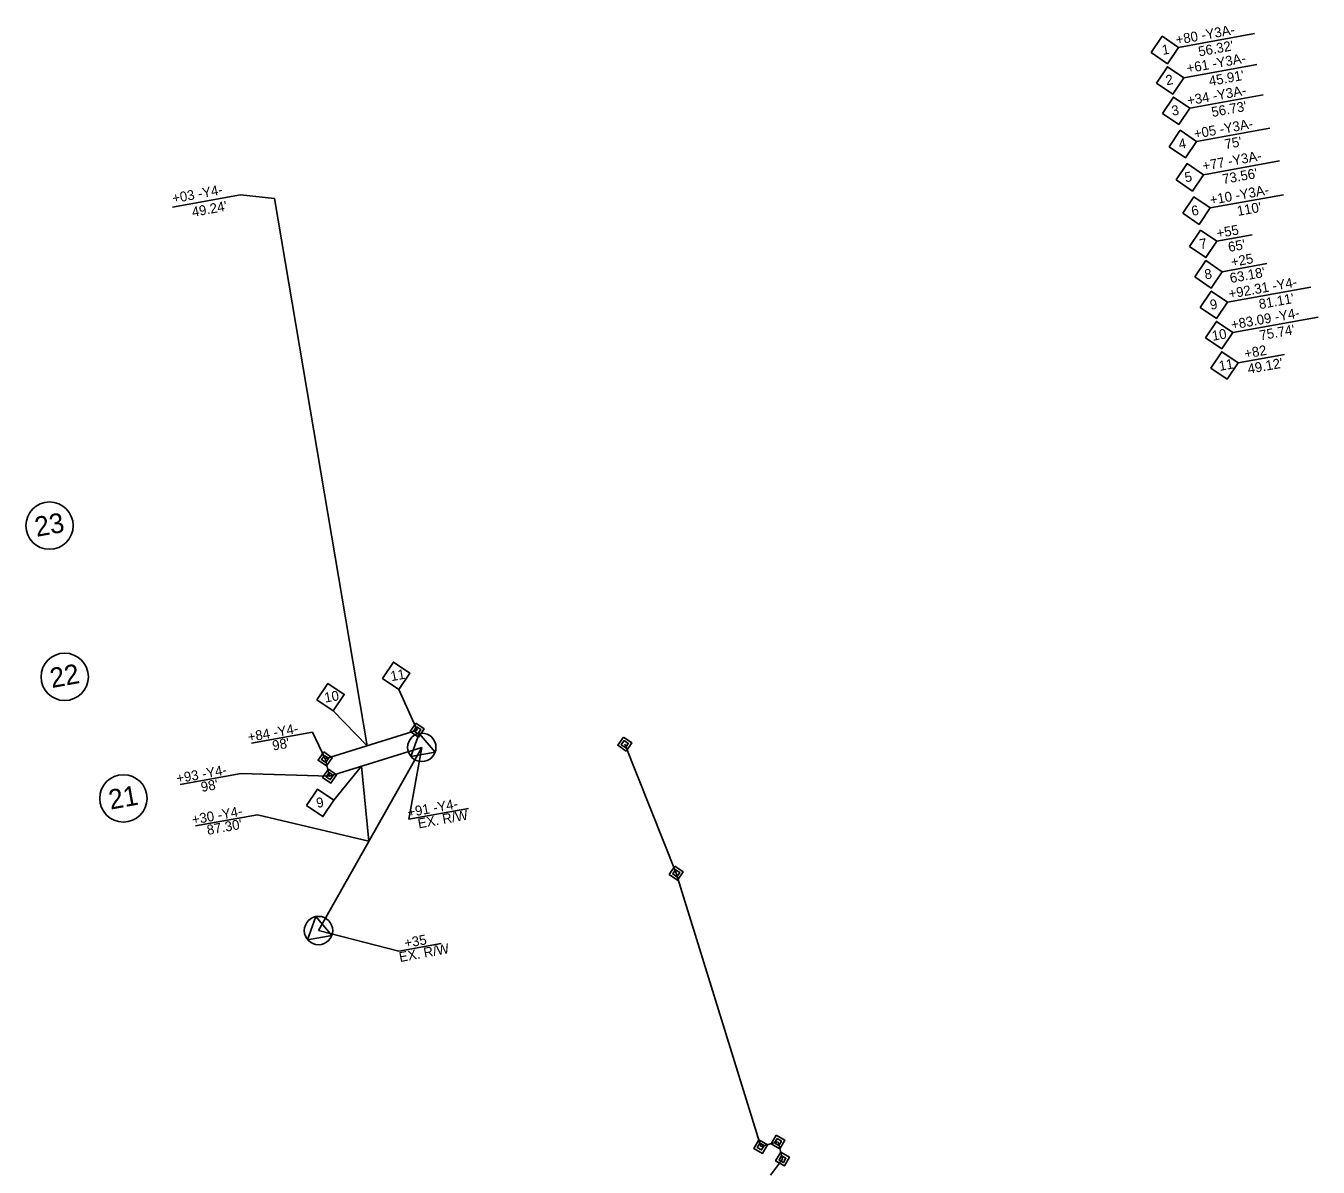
# Model space of a CAD drawing. Extents: x 1618217 to 1621927, y 897445 to 899141.
# Drawn here: x 1621192 to 1621847, y 898125 to 898703 of the extents above; entities that cross this region are included whole.
import ezdxf

# ---------------------------------------------------------------- set-up
doc = ezdxf.new("R2010")
doc.units = 0
for name, color, linetype in [('Prop Easement Construction', 7, 'Continuous'), ('Prop Easement Construction Station Offsets', 7, 'Continuous'), ('Prop Easement Permanent Utility', 7, 'Continuous'), ('Prop Easement Permanent Utility Station Offsets', 7, 'Continuous'), ('Prop Easement Temporary Drainage Station Offsets', 7, 'Continuous'), ('Prop Parcel Number CELL', 7, 'Continuous'), ('Prop ROW Marker CELL', 7, 'Continuous'), ('Prop ROW Permanent Easement CELL', 7, 'Continuous'), ('Prop ROW RW Lines', 7, 'Continuous'), ('Prop ROW Station Offsets', 7, 'Continuous')]:
    doc.layers.add(name, color=color, linetype=linetype)

msp = doc.modelspace()

# ---------------------------------------------------------------- linework, layer by layer
at = {"layer": 'Prop Easement Construction'}
for p, q in [((1621365.15, 898338.17), (1621318.33, 898615.59)), ((1621366.11, 898289.87), (1621362.35, 898327.88))]:
    msp.add_line(p, q, dxfattribs=at)
at = {"layer": 'Prop Easement Construction Station Offsets'}
for p, q in [((1621782.34, 898661.5), (1621819.53, 898668.23)), ((1621785.78, 898644.61), (1621822.97, 898651.34)), ((1621266.61, 898611.28), (1621301.06, 898617.52)), ((1621301.06, 898617.52), (1621318.33, 898615.59)), ((1621792.66, 898610.85), (1621829.85, 898617.58)), ((1621796.1, 898593.96), (1621814.01, 898597.2)), ((1621801.46, 898563.15), (1621843.63, 898570.78)), ((1621804.15, 898547.74), (1621847.41, 898555.57)), ((1621365.15, 898338.17), (1621347.98, 898355.93)), ((1621348.37, 898310.62), (1621362.35, 898327.88)), ((1621278.26, 898297.6), (1621309.57, 898303.27)), ((1621309.57, 898303.27), (1621366.11, 898289.87))]:
    msp.add_line(p, q, dxfattribs=at)
for points in [[(1621768.46, 898658.82), (1621776.74, 898653.21), (1621782.34, 898661.5), (1621774.06, 898667.1)], [(1621771.9, 898641.93), (1621780.18, 898636.33), (1621785.78, 898644.61), (1621777.5, 898650.22)], [(1621778.78, 898608.17), (1621787.06, 898602.56), (1621792.66, 898610.85), (1621784.38, 898616.45)], [(1621782.22, 898591.28), (1621790.5, 898585.68), (1621796.1, 898593.96), (1621787.82, 898599.57)], [(1621787.58, 898560.47), (1621795.86, 898554.86), (1621801.46, 898563.15), (1621793.18, 898568.75)], [(1621790.26, 898545.06), (1621798.54, 898539.46), (1621804.15, 898547.74), (1621795.86, 898553.34)], [(1621339.7, 898361.53), (1621347.98, 898355.93), (1621353.58, 898364.21), (1621345.3, 898369.81)], [(1621334.48, 898307.94), (1621342.76, 898302.34), (1621348.37, 898310.62), (1621340.08, 898316.23)]]:
    msp.add_lwpolyline(points, close=True, dxfattribs=at)
at = {"layer": 'Prop Easement Permanent Utility'}
for p, q in [((1621343.89, 898331.54), (1621390.59, 898346.11)), ((1621521.92, 898273.6), (1621495.84, 898339.08)), ((1621346.21, 898322.84), (1621392.93, 898337.42)), ((1621346.21, 898322.84), (1621343.89, 898331.54)), ((1621564.76, 898135.04), (1621521.92, 898273.6)), ((1621573.5, 898137.36), (1621564.76, 898135.04)), ((1621573.54, 898137.37), (1621575.87, 898128.67)), ((1621569.74, 898120.49), (1621575.83, 898128.66))]:
    msp.add_line(p, q, dxfattribs=at)
at = {"layer": 'Prop Easement Permanent Utility Station Offsets'}
for p, q in [((1621779.28, 898676.88), (1621816.26, 898683.57)), ((1621789.22, 898627.73), (1621827.78, 898634.71)), ((1621806.83, 898532.33), (1621830.4, 898536.6)), ((1621390.59, 898346.11), (1621381.24, 898366.75)), ((1621306.54, 898339.45), (1621337.54, 898345.06)), ((1621337.54, 898345.06), (1621343.89, 898331.54)), ((1621270.43, 898318.51), (1621301.33, 898324.1)), ((1621301.33, 898324.1), (1621346.21, 898322.84))]:
    msp.add_line(p, q, dxfattribs=at)
for points in [[(1621765.4, 898674.2), (1621773.68, 898668.6), (1621779.28, 898676.88), (1621771, 898682.48)], [(1621775.34, 898625.05), (1621783.62, 898619.45), (1621789.22, 898627.73), (1621780.94, 898633.33)], [(1621792.94, 898529.65), (1621801.22, 898524.05), (1621806.83, 898532.33), (1621798.54, 898537.93)], [(1621372.95, 898372.35), (1621381.24, 898366.75), (1621386.84, 898375.03), (1621378.56, 898380.64)]]:
    msp.add_lwpolyline(points, close=True, dxfattribs=at)
at = {"layer": 'Prop Easement Temporary Drainage Station Offsets'}
msp.add_line((1621798.78, 898578.56), (1621821.36, 898582.64), dxfattribs=at)
msp.add_lwpolyline([(1621784.9, 898575.88), (1621793.18, 898570.27), (1621798.78, 898578.56), (1621790.5, 898584.16)], close=True, dxfattribs=at)
at = {"layer": 'Prop Parcel Number CELL'}
for p, q in [((1621204.18, 898449.81), (1621204.18, 898449.81)), ((1621211.87, 898373.17), (1621211.87, 898373.17)), ((1621241.63, 898311.53), (1621241.63, 898311.53))]:
    msp.add_line(p, q, dxfattribs=at)
for centre in [(1621204.18, 898449.81), (1621211.87, 898373.17), (1621241.63, 898311.53)]:
    msp.add_circle(centre, 12, dxfattribs=at)
at = {"layer": 'Prop ROW Marker CELL'}
for p, q in [((1621392.93, 898337.42), (1621392.93, 898337.42)), ((1621340.55, 898244.54), (1621340.55, 898244.54)), ((1621573.5, 898137.36), (1621573.5, 898137.36)), ((1621564.76, 898135.04), (1621564.76, 898135.04)), ((1621575.83, 898128.66), (1621575.83, 898128.66))]:
    msp.add_line(p, q, dxfattribs=at)
for points in [[(1621387.42, 898332.76), (1621391.65, 898344.5), (1621399.72, 898334.99)], [(1621335.04, 898239.89), (1621339.27, 898251.63), (1621347.34, 898242.11)]]:
    msp.add_lwpolyline(points, close=True, dxfattribs=at)
for centre in [(1621392.93, 898337.42), (1621340.55, 898244.54)]:
    msp.add_circle(centre, 7.2, dxfattribs=at)
at = {"layer": 'Prop ROW Permanent Easement CELL'}
for p, q in [((1621390.59, 898346.11), (1621390.59, 898346.11)), ((1621495.84, 898339.08), (1621495.84, 898339.08)), ((1621343.89, 898331.54), (1621343.89, 898331.54)), ((1621346.21, 898322.84), (1621346.21, 898322.84)), ((1621521.92, 898273.6), (1621521.92, 898273.6))]:
    msp.add_line(p, q, dxfattribs=at)
for points in [[(1621389.94, 898349.65), (1621394.13, 898346.75), (1621391.23, 898342.56), (1621387.04, 898345.46)], [(1621390.27, 898347.88), (1621392.36, 898346.43), (1621390.91, 898344.34), (1621388.81, 898345.79)], [(1621495.2, 898342.62), (1621499.38, 898339.72), (1621496.48, 898335.54), (1621492.3, 898338.44)], [(1621495.52, 898340.85), (1621497.61, 898339.4), (1621496.16, 898337.31), (1621494.07, 898338.76)], [(1621343.24, 898335.08), (1621347.43, 898332.18), (1621344.53, 898327.99), (1621340.34, 898330.89)], [(1621343.57, 898333.31), (1621345.66, 898331.86), (1621344.21, 898329.76), (1621342.11, 898331.21)], [(1621345.57, 898326.38), (1621349.76, 898323.48), (1621346.85, 898319.3), (1621342.67, 898322.2)], [(1621345.89, 898324.61), (1621347.98, 898323.16), (1621346.53, 898321.07), (1621344.44, 898322.52)], [(1621521.28, 898277.14), (1621525.46, 898274.24), (1621522.56, 898270.06), (1621518.38, 898272.96)], [(1621521.6, 898275.37), (1621523.69, 898273.92), (1621522.24, 898271.83), (1621520.15, 898273.28)], [(1621563.83, 898138.52), (1621568.24, 898135.97), (1621565.69, 898131.56), (1621561.28, 898134.11)], [(1621564.3, 898136.78), (1621566.5, 898135.51), (1621565.23, 898133.3), (1621563.02, 898134.57)], [(1621572.57, 898140.83), (1621576.98, 898138.29), (1621574.43, 898133.88), (1621570.02, 898136.42)], [(1621573.04, 898139.09), (1621575.24, 898137.82), (1621573.97, 898135.62), (1621571.76, 898136.89)], [(1621574.9, 898132.14), (1621579.31, 898129.59), (1621576.76, 898125.18), (1621572.35, 898127.73)], [(1621575.36, 898130.4), (1621577.57, 898129.13), (1621576.29, 898126.92), (1621574.09, 898128.2)]]:
    msp.add_lwpolyline(points, close=True, dxfattribs=at)
at = {"layer": 'Prop ROW RW Lines'}
msp.add_line((1621340.55, 898244.54), (1621392.93, 898337.42), dxfattribs=at)
at = {"layer": 'Prop ROW Station Offsets'}
for p, q in [((1621776.6, 898692.29), (1621815.1, 898699.26)), ((1621386.36, 898300.99), (1621392.93, 898337.42)), ((1621386.36, 898300.99), (1621416.57, 898306.46)), ((1621381.23, 898234.14), (1621340.55, 898244.54)), ((1621381.23, 898234.14), (1621402.78, 898238.04))]:
    msp.add_line(p, q, dxfattribs=at)
msp.add_lwpolyline([(1621762.72, 898689.61), (1621771, 898684), (1621776.6, 898692.29), (1621768.32, 898697.89)], close=True, dxfattribs=at)

# ---------------------------------------------------------------- texts
at = {"layer": 'Prop Easement Construction Station Offsets'}
for s, rotation, p in [('+34 -Y3A-', 10.25995, (1621781.46, 898662.82)), ('3', 10.25995, (1621773.53, 898657.58)), ("56.73'", 10.25995, (1621793.77, 898656.95)), ('+05 -Y3A-', 10.25995, (1621784.9, 898645.94)), ("75'", 10.25995, (1621800.44, 898640.65)), ('4', 10.25995, (1621777.11, 898640.73)), ('+03 -Y4-', 10.4519, (1621266.9, 898613.22)), ('+10 -Y3A-', 10.25995, (1621792.96, 898612.38)), ("49.24'", 10.4519, (1621276.81, 898606.28)), ('6', 10.25995, (1621783.58, 898606.79)), ("110'", 10.25995, (1621806.73, 898606.78)), ('+55 ', 10.2583, (1621796.37, 898595.49)), ('7', 10.25995, (1621787.7, 898589.99)), ("65'", 10.2583, (1621802.23, 898588.52)), ('+92.31 -Y4-', 10.2583, (1621802.49, 898564.82)), ('9', 10.25995, (1621792.99, 898559.2)), ("81.11'", 10.2583, (1621817.8, 898559.55)), ('+83.09 -Y4-', 10.2583, (1621803.73, 898549.15)), ('10', 10.25995, (1621794, 898543.49)), ("75.74'", 10.2583, (1621818.14, 898543.72)), ('10', 10.25995, (1621343.97, 898360.05)), ('+30 -Y4-', 10.25995, (1621276.85, 898298.22)), ('9', 10.25995, (1621339.89, 898306.67)), ("87.30'", 10.25995, (1621284.41, 898292.98))]:
    msp.add_text(s, height=5, rotation=rotation, dxfattribs=at).set_placement(p)
at = {"layer": 'Prop Easement Permanent Utility Station Offsets'}
for s, rotation, p in [('+61 -Y3A-', 10.25995, (1621781.22, 898679.16)), ("45.91'", 10.25995, (1621792.48, 898672.65)), ('2', 10.25995, (1621770.56, 898673.04)), ('+77 -Y3A-', 10.25995, (1621789.21, 898629.66)), ('5', 10.25995, (1621780.16, 898623.83)), ("73.56'", 10.25995, (1621799.29, 898622.93)), ('+82', 10.2583, (1621810.45, 898534.47)), ('11', 10.25995, (1621797.5, 898528.23)), ("49.12'", 10.2583, (1621812.1, 898526.73)), ('11', 10.25995, (1621377.52, 898370.93)), ('+84 -Y4-', 10.2583, (1621305.17, 898340.11)), ("98'", 10.2583, (1621317.6, 898335.76)), ('+93 -Y4-', 10.2583, (1621268.96, 898319.13)), ("98'", 10.2583, (1621281.38, 898314.78))]:
    msp.add_text(s, height=5, rotation=rotation, dxfattribs=at).set_placement(p)
at = {"layer": 'Prop Easement Temporary Drainage Station Offsets'}
for s, rotation, p in [('+25', 10.2583, (1621803.68, 898580.93)), ('8', 10.25995, (1621790.24, 898574.59)), ("63.18'", 10.2583, (1621803.08, 898572.78))]:
    msp.add_text(s, height=5, rotation=rotation, dxfattribs=at).set_placement(p)
at = {"layer": 'Prop Parcel Number CELL'}
for s, p in [('23', (1621197.64, 898444.09)), ('22', (1621205.34, 898367.45)), ('21', (1621235.1, 898305.81))]:
    msp.add_text(s, height=10, rotation=10.2583, dxfattribs=at).set_placement(p)
at = {"layer": 'Prop ROW Station Offsets'}
for s, rotation, p in [('+80 -Y3A-', 10.2583, (1621775.66, 898693.6)), ('1', 10.25995, (1621768.65, 898688.43)), ("56.32'", 10.2583, (1621787.11, 898687.64)), ('+91 -Y4-', 10.2583, (1621386.14, 898301.93)), ('EX. R/W', 10.2583, (1621391.39, 898296.28)), ('+35', 10.2583, (1621384.57, 898235.63)), ('EX. R/W', 10.2583, (1621381.87, 898228.54))]:
    msp.add_text(s, height=5, rotation=rotation, dxfattribs=at).set_placement(p)

doc.saveas('drawing.dxf')
